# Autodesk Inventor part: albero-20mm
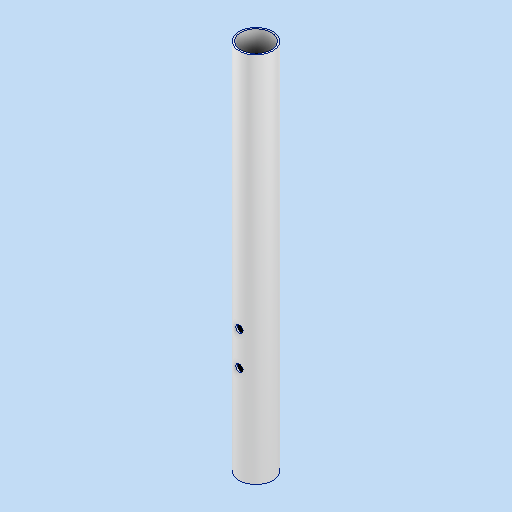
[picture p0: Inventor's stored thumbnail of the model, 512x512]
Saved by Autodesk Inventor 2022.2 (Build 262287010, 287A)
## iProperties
Created: 2025-03
Part Number: albero-20mm
Material: Alluminio 6061
Document SubType Name: Modeling
Designer: 18907419
Density: 2.7 g/cm^3
Appearance: Default
Author: 18907419
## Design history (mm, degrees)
feature "Solido1"
node "Solido2"
